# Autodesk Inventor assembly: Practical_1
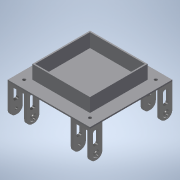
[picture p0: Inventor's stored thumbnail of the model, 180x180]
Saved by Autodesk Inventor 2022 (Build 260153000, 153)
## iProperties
Created: 2016-08
Part Number: Practical_1
Document SubType Name: Weldment
Designer: Gaurav
Weld Material: Welded Aluminum-6061
Author: Gaurav
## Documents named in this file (3)
- F:\My Data\Books_Final Books\2021_Books\Autodesk_Inventor_2022_Black_Book Folder\Autodesk Inventor_Resources_Student\Chapter 11\Practical_1.iam
- F:\My Data\Books_Final Books\2021_Books\Autodesk_Inventor_2022_Black_Book Folder\Autodesk Inventor_Resources_Student\Chapter 11\Practical_1\Base.ipt
- F:\My Data\Books_Final Books\2021_Books\Autodesk_Inventor_2022_Black_Book Folder\Autodesk Inventor_Resources_Student\Chapter 11\Practical_1\Frame.ipt
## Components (5 placed, 2 different names)
1. Base:1 — Mate:1, Flush:1, Flush:2
2. Frame:1 — Mate:1, Flush:1, Flush:2
3. Frame:2
4. Frame:3
5. Frame:4
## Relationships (3: Flush 2, Mate 1)
- Mate:1: Base:1 ↔ Frame:1
- Flush:1: Base:1 ↔ Frame:1
- Flush:2: Base:1 ↔ Frame:1
